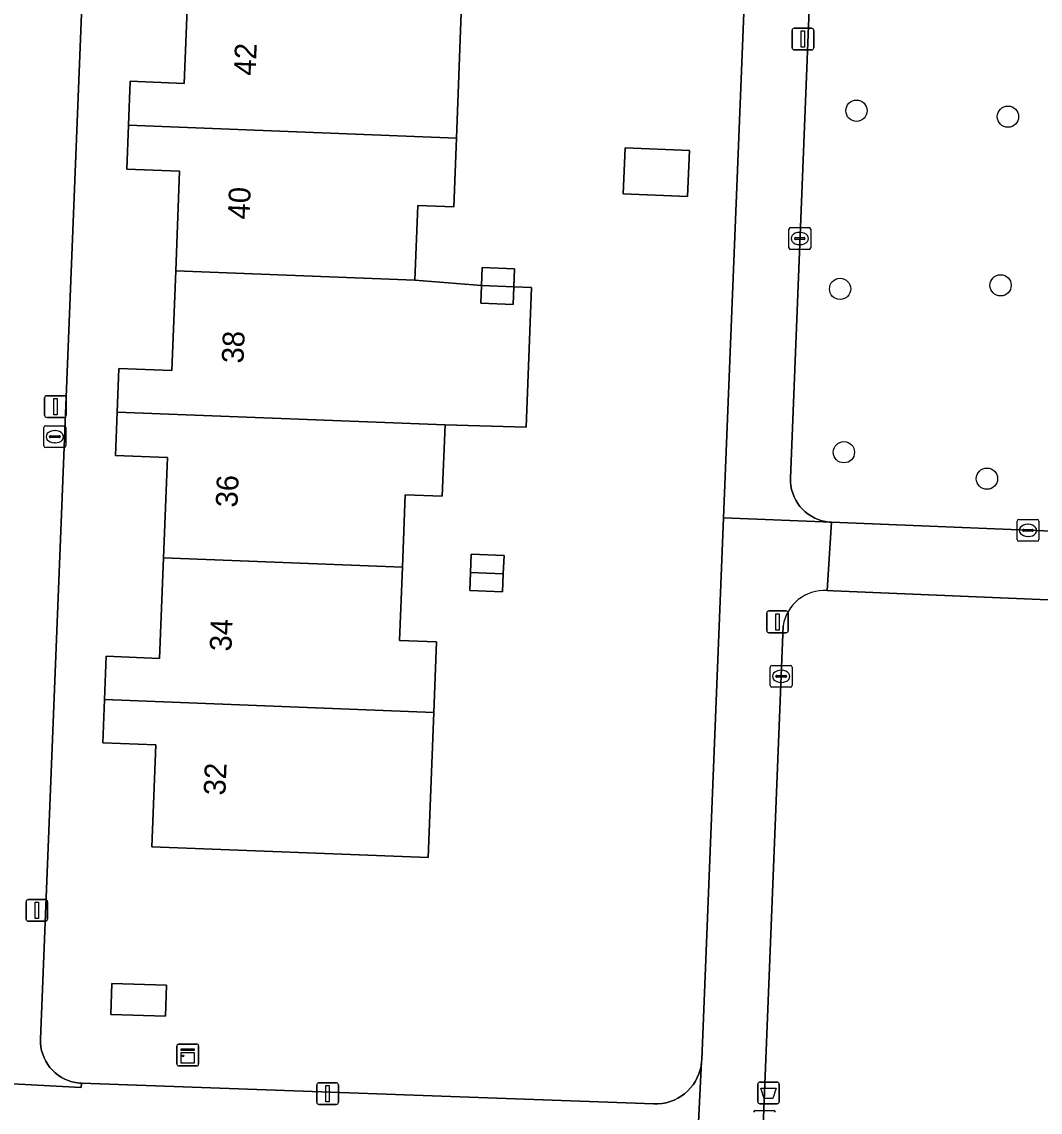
# Model space of a CAD drawing. Extents: x 160786 to 161429, y 386828 to 387485.
# Drawn here: x 161091.8 to 161138.7, y 387047.4 to 387097.5 of the extents above; entities that cross this region are included whole.
import ezdxf

# ---------------------------------------------------------------- set-up
doc = ezdxf.new("R2010")
doc.units = 0
for name, color, linetype in [('IMGEO_Afvalbak', 7, 'Continuous'), ('IMGEO_Boom', 7, 'Continuous'), ('IMGEO_Erf', 7, 'Continuous'), ('IMGEO_Groenvoorziening', 7, 'Continuous'), ('IMGEO_Kast', 7, 'Continuous'), ('IMGEO_Kolk', 7, 'Continuous'), ('IMGEO_Lichtmast', 7, 'Continuous'), ('IMGEO_Pand', 7, 'Continuous'), ('IMGEO_Pand_nummerreeks', 7, 'Continuous'), ('IMGEO_Rioolput', 7, 'Continuous'), ('IMGEO_Voetpad_open', 7, 'Continuous')]:
    doc.layers.add(name, color=color, linetype=linetype)

msp = doc.modelspace()

# ---------------------------------------------------------------- linework, layer by layer
at = {"layer": 'IMGEO_Afvalbak'}
for p, q in [((161125.771, 387048.763), (161126.561, 387048.763)), ((161126.561, 387048.763), (161125.771, 387048.763)), ((161125.671, 387047.863), (161125.671, 387048.663)), ((161125.671, 387048.663), (161125.671, 387047.863)), ((161126.661, 387048.663), (161126.661, 387047.863)), ((161126.661, 387047.863), (161126.661, 387048.663)), ((161126.561, 387047.763), (161125.771, 387047.763)), ((161125.771, 387047.763), (161126.561, 387047.763))]:
    msp.add_line(p, q, dxfattribs=at)
msp.add_lwpolyline([(161125.814, 387048.477), (161126.518, 387048.477), (161126.369, 387048.007), (161125.963, 387048.007), (161125.814, 387048.477)], dxfattribs=at)
for centre, start, end in [((161125.771, 387048.663), 90, 180), ((161125.771, 387048.663), 90, 180), ((161126.561, 387048.663), 0, 90), ((161126.561, 387048.663), 360, 90), ((161125.771, 387047.863), 180, 270), ((161125.771, 387047.863), 180, 270), ((161126.561, 387047.863), 270, 0), ((161126.561, 387047.863), 270, 0)]:
    msp.add_arc(centre, 0.1, start, end, dxfattribs=at)
at = {"layer": 'IMGEO_Boom'}
for centre in [(161130.212, 387093.447), (161137.176, 387093.174), (161136.837, 387085.415), (161129.459, 387085.253), (161129.634, 387077.738), (161136.21, 387076.52)]:
    msp.add_circle(centre, 0.489, dxfattribs=at)
at = {"layer": 'IMGEO_Erf'}
for points in [[(161094.68, 387100.61), (161092.693, 387050.734), (161092.694, 387050.559), (161092.712, 387050.385), (161092.744, 387050.214), (161092.792, 387050.046), (161092.854, 387049.882), (161092.931, 387049.725), (161093.022, 387049.576), (161093.125, 387049.435), (161093.241, 387049.304), (161093.368, 387049.184), (161093.505, 387049.076), (161093.652, 387048.98), (161093.806, 387048.898), (161093.967, 387048.83), (161094.133, 387048.777), (161094.304, 387048.739), (161094.477, 387048.716), (161094.57, 387048.71), (161120.895, 387047.758), (161121.085, 387047.76), (161121.275, 387047.778), (161121.462, 387047.814), (161121.645, 387047.866), (161121.823, 387047.934), (161121.993, 387048.018), (161122.156, 387048.117), (161122.309, 387048.23), (161122.452, 387048.356), (161122.583, 387048.494), (161122.7, 387048.644), (161122.804, 387048.803), (161122.894, 387048.971), (161122.968, 387049.147), (161123.026, 387049.328), (161123.067, 387049.514), (161123.092, 387049.703), (161123.098, 387049.797), (161124.099, 387074.719), (161127.175, 387151.273)], [(161112.071, 387098.797), (161111.813, 387092.188), (161111.69, 387089.03), (161110.043, 387089.094), (161109.909, 387085.648), (161112.969, 387085.409), (161113.001, 387086.236), (161114.484, 387086.178), (161114.452, 387085.351), (161115.266, 387085.317), (161115.024, 387078.887), (161111.297, 387078.995), (161111.168, 387075.71), (161109.465, 387075.777), (161109.335, 387072.443), (161109.203, 387069.076), (161110.907, 387069.009), (161110.78, 387065.768), (161110.519, 387059.095), (161097.808, 387059.592), (161097.991, 387064.277), (161095.561, 387064.372), (161095.639, 387066.36), (161095.717, 387068.351), (161098.164, 387068.255), (161098.345, 387072.872), (161098.525, 387077.488), (161096.14, 387077.581), (161096.218, 387079.585), (161096.297, 387081.591), (161098.732, 387081.496), (161098.911, 387086.078), (161099.09, 387090.661), (161096.655, 387090.756), (161096.734, 387092.778), (161096.813, 387094.802), (161099.297, 387094.705), (161099.476, 387099.29)]]:
    msp.add_lwpolyline(points, dxfattribs=at)
for points in [[(161119.489, 387089.621), (161119.572, 387091.737), (161122.531, 387091.622), (161122.448, 387089.506)], [(161112.466, 387072.204), (161112.499, 387073.041), (161114.005, 387072.983), (161113.973, 387072.146), (161113.94, 387071.323), (161112.434, 387071.382)], [(161098.434, 387051.791), (161095.926, 387051.873), (161095.973, 387053.305), (161098.481, 387053.222)]]:
    msp.add_lwpolyline(points, close=True, dxfattribs=at)
at = {"layer": 'IMGEO_Groenvoorziening'}
for points in [[(161131.407, 387182.665), (161131.384, 387182.078), (161127.179, 387076.544), (161127.18, 387076.369), (161127.198, 387076.195), (161127.23, 387076.024), (161127.278, 387075.856), (161127.34, 387075.692), (161127.417, 387075.535), (161127.508, 387075.386), (161127.611, 387075.245), (161127.727, 387075.114), (161127.854, 387074.994), (161127.991, 387074.886), (161128.138, 387074.79), (161128.292, 387074.708), (161128.453, 387074.64), (161128.619, 387074.587), (161128.79, 387074.549), (161128.963, 387074.526), (161129.056, 387074.52), (161141.468, 387074.009), (161145.662, 387177.089)], [(161150.759, 387070.455), (161129.133, 387071.365), (161128.864, 387071.378)], [(161126.838, 387069.748), (161124.044, 387000), (161122.553, 386963.852)]]:
    msp.add_lwpolyline(points, dxfattribs=at)
msp.add_arc((161128.747, 387069.45), 1.932, 86.5201, 171.1161, dxfattribs=at)
at = {"layer": 'IMGEO_Kast'}
for p, q in [((161098.961, 387049.58), (161098.961, 387050.421)), ((161098.961, 387050.421), (161098.961, 387049.58)), ((161099.036, 387050.505), (161099.877, 387050.505)), ((161099.877, 387050.505), (161099.036, 387050.505)), ((161099.961, 387050.43), (161099.961, 387049.589)), ((161099.961, 387049.589), (161099.961, 387050.43)), ((161099.886, 387049.505), (161099.045, 387049.505)), ((161099.045, 387049.505), (161099.886, 387049.505))]:
    msp.add_line(p, q, dxfattribs=at)
for points in [[(161099.156, 387050.295), (161099.756, 387050.295), (161099.756, 387050.21), (161099.156, 387050.21), (161099.156, 387050.295)], [(161099.156, 387050.12), (161099.756, 387050.12), (161099.756, 387049.631), (161099.156, 387049.631), (161099.156, 387050.12)]]:
    msp.add_lwpolyline(points, dxfattribs=at)
msp.add_circle((161099.24, 387049.969), 0.0377, dxfattribs=at)
for centre, start, end in [((161099.039, 387050.427), 92.4484, 184.2845), ((161099.039, 387050.427), 92.4484, 184.2845), ((161099.883, 387050.427), 2.4484, 94.2845), ((161099.883, 387050.427), 2.4484, 94.2845), ((161099.039, 387049.583), 182.4484, 274.2845), ((161099.039, 387049.583), 182.4484, 274.2845), ((161099.883, 387049.583), 272.4484, 4.2845), ((161099.883, 387049.583), 272.4484, 4.2845)]:
    msp.add_arc(centre, 0.0779, start, end, dxfattribs=at)
at = {"layer": 'IMGEO_Kolk'}
for p, q in [((161127.105, 387087.142), (161127.105, 387087.994)), ((161127.18, 387088.068), (161128.032, 387088.068)), ((161127.593, 387087.848), (161127.618, 387087.848)), ((161128.106, 387087.994), (161128.106, 387087.142)), ((161127.364, 387087.562), (161127.364, 387087.574)), ((161127.802, 387087.525), (161127.404, 387087.525)), ((161127.407, 387087.611), (161127.805, 387087.611)), ((161127.848, 387087.574), (161127.848, 387087.562)), ((161128.032, 387087.068), (161127.18, 387087.068)), ((161127.616, 387087.288), (161127.591, 387087.288)), ((161137.599, 387073.716), (161137.599, 387074.568)), ((161137.674, 387074.642), (161138.526, 387074.642)), ((161138.087, 387074.422), (161138.112, 387074.422)), ((161138.6, 387074.568), (161138.6, 387073.716)), ((161137.858, 387074.136), (161137.858, 387074.148)), ((161138.296, 387074.099), (161137.898, 387074.099)), ((161137.901, 387074.185), (161138.299, 387074.185)), ((161138.11, 387073.862), (161138.085, 387073.862)), ((161138.342, 387074.148), (161138.342, 387074.136)), ((161138.526, 387073.642), (161137.674, 387073.642)), ((161126.25, 387067.001), (161126.25, 387067.853)), ((161126.325, 387067.927), (161127.177, 387067.927)), ((161127.251, 387067.853), (161127.251, 387067.001)), ((161126.509, 387067.421), (161126.509, 387067.433)), ((161126.947, 387067.384), (161126.549, 387067.384)), ((161126.552, 387067.47), (161126.95, 387067.47)), ((161126.738, 387067.707), (161126.763, 387067.707)), ((161126.993, 387067.433), (161126.993, 387067.421)), ((161127.177, 387066.927), (161126.325, 387066.927)), ((161126.761, 387067.147), (161126.736, 387067.147)), ((161125.556, 387047.452), (161126.408, 387047.452))]:
    msp.add_line(p, q, dxfattribs=at)
for points in [[(161127.105, 387087.142), (161127.105, 387087.994)], [(161127.18, 387088.068), (161128.032, 387088.068)], [(161128.106, 387087.994), (161128.106, 387087.142)], [(161128.032, 387087.068), (161127.18, 387087.068)], [(161137.599, 387073.716), (161137.599, 387074.568)], [(161137.674, 387074.642), (161138.526, 387074.642)], [(161138.6, 387074.568), (161138.6, 387073.716)], [(161138.526, 387073.642), (161137.674, 387073.642)], [(161126.25, 387067.001), (161126.25, 387067.853)], [(161126.325, 387067.927), (161127.177, 387067.927)], [(161127.251, 387067.853), (161127.251, 387067.001)], [(161127.177, 387066.927), (161126.325, 387066.927)], [(161125.556, 387047.452), (161126.408, 387047.452)]]:
    msp.add_lwpolyline(points, dxfattribs=at)
for centre, radius, start, end in [((161127.182, 387087.992), 0.0765, 91.552, 178.448), ((161127.182, 387087.992), 0.0765, 91.552, 178.448), ((161128.03, 387087.992), 0.0765, 1.552, 88.448), ((161128.03, 387087.992), 0.0765, 1.552, 88.448), ((161127.404, 387087.571), 0.0403, 85.8775, 175.7526), ((161127.401, 387087.561), 0.0366, 178.938, 274.7102), ((161127.805, 387087.568), 0.043, 264.8664, 352.4533), ((161127.809, 387087.573), 0.0386, 1.7309, 96.639), ((161127.182, 387087.144), 0.0765, 181.552, 268.448), ((161127.182, 387087.144), 0.0765, 181.552, 268.448), ((161128.03, 387087.144), 0.0765, 271.552, 358.448), ((161128.03, 387087.144), 0.0765, 271.552, 358.448), ((161137.676, 387074.566), 0.0765, 91.552, 178.448), ((161137.676, 387074.566), 0.0765, 91.552, 178.448), ((161138.524, 387074.566), 0.0765, 1.552, 88.448), ((161138.524, 387074.566), 0.0765, 1.552, 88.448), ((161137.898, 387074.145), 0.0403, 85.8775, 175.7526), ((161137.895, 387074.135), 0.0366, 178.938, 274.7102), ((161138.299, 387074.142), 0.043, 264.8664, 352.4533), ((161138.303, 387074.147), 0.0386, 1.7309, 96.639), ((161137.676, 387073.718), 0.0765, 181.552, 268.448), ((161137.676, 387073.718), 0.0765, 181.552, 268.448), ((161138.524, 387073.718), 0.0765, 271.552, 358.448), ((161138.524, 387073.718), 0.0765, 271.552, 358.448), ((161126.327, 387067.851), 0.0765, 91.552, 178.448), ((161126.327, 387067.851), 0.0765, 91.552, 178.448), ((161127.175, 387067.851), 0.0765, 1.552, 88.448), ((161127.175, 387067.851), 0.0765, 1.552, 88.448), ((161126.549, 387067.43), 0.0403, 85.8775, 175.7526), ((161126.546, 387067.42), 0.0366, 178.938, 274.7102), ((161126.95, 387067.427), 0.043, 264.8664, 352.4533), ((161126.954, 387067.432), 0.0386, 1.7309, 96.639), ((161126.327, 387067.003), 0.0765, 181.552, 268.448), ((161126.327, 387067.003), 0.0765, 181.552, 268.448), ((161127.175, 387067.003), 0.0765, 271.552, 358.448), ((161127.175, 387067.003), 0.0765, 271.552, 358.448), ((161125.558, 387047.376), 0.0765, 91.552, 178.448), ((161125.558, 387047.376), 0.0765, 91.552, 178.448), ((161126.406, 387047.376), 0.0765, 1.552, 88.448), ((161126.406, 387047.376), 0.0765, 1.552, 88.448)]:
    msp.add_arc(centre, radius, start, end, dxfattribs=at)
for centre, major_axis, ratio, start_param, end_param in [((161127.592, 387087.568), (-0.387, 0.002), 0.722429, 4.712389, 7.853982), ((161127.617, 387087.568), (-0.39, 0.002), 0.717154, 1.570796, 4.712389), ((161138.086, 387074.142), (-0.387, 0.002), 0.722429, 4.712389, 7.853982), ((161138.111, 387074.142), (-0.39, 0.002), 0.717154, 1.570796, 4.712389), ((161126.737, 387067.427), (-0.387, 0.002), 0.722429, 4.712389, 7.853982), ((161126.762, 387067.427), (-0.39, 0.002), 0.717154, 1.570796, 4.712389)]:
    msp.add_ellipse(centre, major_axis=major_axis, ratio=ratio, start_param=start_param, end_param=end_param, dxfattribs=at)
at = {"layer": 'IMGEO_Lichtmast'}
for p, q in [((161127.254, 387096.342), (161127.254, 387097.142)), ((161127.254, 387097.142), (161127.254, 387096.342)), ((161127.354, 387097.242), (161128.144, 387097.242)), ((161128.144, 387097.242), (161127.354, 387097.242)), ((161128.244, 387097.142), (161128.244, 387096.342)), ((161128.244, 387096.342), (161128.244, 387097.142)), ((161128.144, 387096.242), (161127.354, 387096.242)), ((161127.354, 387096.242), (161128.144, 387096.242)), ((161092.981, 387080.339), (161093.771, 387080.339)), ((161093.771, 387080.339), (161092.981, 387080.339)), ((161092.881, 387079.439), (161092.881, 387080.239)), ((161092.881, 387080.239), (161092.881, 387079.439)), ((161093.871, 387080.239), (161093.871, 387079.439)), ((161093.871, 387079.439), (161093.871, 387080.239)), ((161093.771, 387079.339), (161092.981, 387079.339)), ((161092.981, 387079.339), (161093.771, 387079.339)), ((161126.085, 387069.534), (161126.085, 387070.334)), ((161126.085, 387070.334), (161126.085, 387069.534)), ((161126.185, 387070.434), (161126.975, 387070.434)), ((161126.975, 387070.434), (161126.185, 387070.434)), ((161127.075, 387070.334), (161127.075, 387069.534)), ((161127.075, 387069.534), (161127.075, 387070.334)), ((161126.975, 387069.434), (161126.185, 387069.434)), ((161126.185, 387069.434), (161126.975, 387069.434)), ((161092.028, 387056.261), (161092.028, 387057.061)), ((161092.028, 387057.061), (161092.028, 387056.261)), ((161092.128, 387057.161), (161092.918, 387057.161)), ((161092.918, 387057.161), (161092.128, 387057.161)), ((161093.018, 387057.061), (161093.018, 387056.261)), ((161093.018, 387056.261), (161093.018, 387057.061)), ((161092.918, 387056.161), (161092.128, 387056.161)), ((161092.128, 387056.161), (161092.918, 387056.161)), ((161105.497, 387048.732), (161106.287, 387048.732)), ((161106.287, 387048.732), (161105.497, 387048.732)), ((161105.397, 387047.832), (161105.397, 387048.632)), ((161105.397, 387048.632), (161105.397, 387047.832)), ((161106.387, 387048.632), (161106.387, 387047.832)), ((161106.387, 387047.832), (161106.387, 387048.632)), ((161106.287, 387047.732), (161105.497, 387047.732)), ((161105.497, 387047.732), (161106.287, 387047.732))]:
    msp.add_line(p, q, dxfattribs=at)
for points in [[(161127.674, 387097.117), (161127.824, 387097.117), (161127.824, 387096.367), (161127.674, 387096.367), (161127.674, 387097.117)], [(161093.301, 387080.214), (161093.451, 387080.214), (161093.451, 387079.464), (161093.301, 387079.464), (161093.301, 387080.214)], [(161126.505, 387070.309), (161126.655, 387070.309), (161126.655, 387069.559), (161126.505, 387069.559), (161126.505, 387070.309)], [(161092.448, 387057.036), (161092.598, 387057.036), (161092.598, 387056.286), (161092.448, 387056.286), (161092.448, 387057.036)], [(161105.817, 387048.607), (161105.967, 387048.607), (161105.967, 387047.857), (161105.817, 387047.857), (161105.817, 387048.607)]]:
    msp.add_lwpolyline(points, dxfattribs=at)
for centre, start, end in [((161127.354, 387097.142), 90, 180), ((161127.354, 387097.142), 90, 180), ((161128.144, 387097.142), 0, 90), ((161128.144, 387097.142), 360, 90), ((161127.354, 387096.342), 180, 270), ((161127.354, 387096.342), 180, 270), ((161128.144, 387096.342), 270, 0), ((161128.144, 387096.342), 270, 0), ((161092.981, 387080.239), 90, 180), ((161092.981, 387080.239), 90, 180), ((161093.771, 387080.239), 0, 90), ((161093.771, 387080.239), 360, 90), ((161092.981, 387079.439), 180, 270), ((161092.981, 387079.439), 180, 270), ((161093.771, 387079.439), 270, 0), ((161093.771, 387079.439), 270, 0), ((161126.185, 387070.334), 90, 180), ((161126.185, 387070.334), 90, 180), ((161126.975, 387070.334), 0, 90), ((161126.975, 387070.334), 360, 90), ((161126.185, 387069.534), 180, 270), ((161126.185, 387069.534), 180, 270), ((161126.975, 387069.534), 270, 0), ((161126.975, 387069.534), 270, 0), ((161092.128, 387057.061), 90, 180), ((161092.128, 387057.061), 90, 180), ((161092.918, 387057.061), 0, 90), ((161092.918, 387057.061), 360, 90), ((161092.128, 387056.261), 180, 270), ((161092.128, 387056.261), 180, 270), ((161092.918, 387056.261), 270, 0), ((161092.918, 387056.261), 270, 0), ((161105.497, 387048.632), 90, 180), ((161105.497, 387048.632), 90, 180), ((161106.287, 387048.632), 0, 90), ((161106.287, 387048.632), 360, 90), ((161105.497, 387047.832), 180, 270), ((161105.497, 387047.832), 180, 270), ((161106.287, 387047.832), 270, 0), ((161106.287, 387047.832), 270, 0)]:
    msp.add_arc(centre, 0.1, start, end, dxfattribs=at)
at = {"layer": 'IMGEO_Pand'}
for points in [[(161111.813, 387092.188), (161112.071, 387098.797), (161099.476, 387099.29), (161099.297, 387094.705), (161096.813, 387094.802), (161096.734, 387092.778)], [(161111.813, 387092.188), (161096.734, 387092.778), (161096.655, 387090.756), (161099.09, 387090.661), (161098.911, 387086.078), (161109.909, 387085.648), (161110.043, 387089.094), (161111.69, 387089.03)], [(161119.489, 387089.621), (161122.448, 387089.506), (161122.531, 387091.622), (161119.572, 387091.737)], [(161114.452, 387085.351), (161114.42, 387084.53), (161112.937, 387084.587), (161112.969, 387085.409), (161109.909, 387085.648), (161098.911, 387086.078), (161098.732, 387081.496), (161096.297, 387081.591), (161096.218, 387079.585), (161111.297, 387078.995), (161115.024, 387078.887), (161115.266, 387085.317)], [(161112.969, 387085.409), (161114.452, 387085.351), (161114.484, 387086.178), (161113.001, 387086.236)], [(161114.452, 387085.351), (161112.969, 387085.409), (161112.937, 387084.587), (161114.42, 387084.53)], [(161111.297, 387078.995), (161096.218, 387079.585), (161096.14, 387077.581), (161098.525, 387077.488), (161098.345, 387072.872), (161109.335, 387072.443), (161109.465, 387075.777), (161111.168, 387075.71)], [(161109.335, 387072.443), (161098.345, 387072.872), (161098.164, 387068.255), (161095.717, 387068.351), (161095.639, 387066.36), (161110.78, 387065.768), (161110.907, 387069.009), (161109.203, 387069.076)], [(161112.466, 387072.204), (161113.973, 387072.146), (161114.005, 387072.983), (161112.499, 387073.041)], [(161113.973, 387072.146), (161112.466, 387072.204), (161112.434, 387071.382), (161113.94, 387071.323)], [(161095.639, 387066.36), (161095.561, 387064.372), (161097.991, 387064.277), (161097.808, 387059.592), (161110.519, 387059.095), (161110.78, 387065.768)], [(161095.926, 387051.873), (161098.434, 387051.791), (161098.481, 387053.222), (161095.973, 387053.305)]]:
    msp.add_lwpolyline(points, close=True, dxfattribs=at)
at = {"layer": 'IMGEO_Rioolput'}
for p, q in [((161092.849, 387078.025), (161092.849, 387078.877)), ((161092.924, 387078.951), (161093.776, 387078.951)), ((161093.85, 387078.877), (161093.85, 387078.025)), ((161093.108, 387078.445), (161093.108, 387078.457)), ((161093.546, 387078.408), (161093.148, 387078.408)), ((161093.151, 387078.494), (161093.549, 387078.494)), ((161093.337, 387078.731), (161093.362, 387078.731)), ((161093.592, 387078.457), (161093.592, 387078.445)), ((161093.776, 387077.951), (161092.924, 387077.951)), ((161093.36, 387078.171), (161093.335, 387078.171))]:
    msp.add_line(p, q, dxfattribs=at)
for points in [[(161092.849, 387078.025), (161092.849, 387078.877)], [(161092.924, 387078.951), (161093.776, 387078.951)], [(161093.85, 387078.877), (161093.85, 387078.025)], [(161093.776, 387077.951), (161092.924, 387077.951)]]:
    msp.add_lwpolyline(points, dxfattribs=at)
for centre, radius, start, end in [((161092.926, 387078.875), 0.0765, 91.552, 178.448), ((161092.926, 387078.875), 0.0765, 91.552, 178.448), ((161093.774, 387078.875), 0.0765, 1.552, 88.448), ((161093.774, 387078.875), 0.0765, 1.552, 88.448), ((161093.148, 387078.454), 0.0403, 85.8775, 175.7526), ((161093.145, 387078.444), 0.0366, 178.938, 274.7102), ((161093.549, 387078.451), 0.043, 264.8664, 352.4533), ((161093.553, 387078.456), 0.0386, 1.7309, 96.639), ((161092.926, 387078.027), 0.0765, 181.552, 268.448), ((161092.926, 387078.027), 0.0765, 181.552, 268.448), ((161093.774, 387078.027), 0.0765, 271.552, 358.448), ((161093.774, 387078.027), 0.0765, 271.552, 358.448)]:
    msp.add_arc(centre, radius, start, end, dxfattribs=at)
for centre, major_axis, ratio, start_param, end_param in [((161093.336, 387078.451), (-0.387, 0.002), 0.722429, 4.712389, 7.853982), ((161093.361, 387078.451), (-0.39, 0.002), 0.717154, 1.570796, 4.712389)]:
    msp.add_ellipse(centre, major_axis=major_axis, ratio=ratio, start_param=start_param, end_param=end_param, dxfattribs=at)
at = {"layer": 'IMGEO_Voetpad_open'}
for points in [[(161127.175, 387151.273), (161124.099, 387074.719), (161129.056, 387074.52), (161128.963, 387074.526), (161128.79, 387074.549), (161128.619, 387074.587), (161128.453, 387074.64), (161128.292, 387074.708), (161128.138, 387074.79), (161127.991, 387074.886), (161127.854, 387074.994), (161127.727, 387075.114), (161127.611, 387075.245), (161127.508, 387075.386), (161127.417, 387075.535), (161127.34, 387075.692), (161127.278, 387075.856), (161127.23, 387076.024), (161127.198, 387076.195), (161127.18, 387076.369), (161127.179, 387076.544), (161131.384, 387182.078)], [(161089.667, 387048.768), (161094.559, 387048.51), (161094.57, 387048.71), (161094.477, 387048.716), (161094.304, 387048.739), (161094.133, 387048.777), (161093.967, 387048.83), (161093.806, 387048.898), (161093.652, 387048.98), (161093.505, 387049.076), (161093.368, 387049.184), (161093.241, 387049.304), (161093.125, 387049.435), (161093.022, 387049.576), (161092.931, 387049.725), (161092.854, 387049.882), (161092.792, 387050.046), (161092.744, 387050.214), (161092.712, 387050.385), (161092.694, 387050.559), (161092.693, 387050.734), (161094.68, 387100.61)], [(161128.864, 387071.378), (161129.056, 387074.52), (161124.099, 387074.719), (161123.098, 387049.797), (161123.092, 387049.703), (161122.751, 387042.869), (161122.753, 387042.692), (161122.596, 387038.706), (161121.076, 387000), (161119.475, 386959.244), (161118.604, 386937.102)], [(161155.473, 387073.431), (161147.279, 387073.767), (161141.468, 387074.009), (161129.056, 387074.52), (161128.864, 387071.378), (161129.133, 387071.365), (161150.759, 387070.455), (161150.793, 387070.458), (161157.068, 387070.064), (161184.654, 387069.093), (161190.576, 387068.744), (161208.66, 387068.005), (161208.877, 387067.997), (161209.096, 387067.988), (161209.41, 387067.975), (161209.768, 387067.943)], [(161120.37, 386911.783), (161120.564, 386917.225), (161120.797, 386923.755), (161120.97, 386928.628), (161121.017, 386929.934), (161121.473, 386936.897), (161122.253, 386956.657), (161122.251, 386956.693), (161122.549, 386963.816), (161122.553, 386963.852), (161124.044, 387000), (161126.838, 387069.748)], [(161123.092, 387049.703), (161123.067, 387049.514), (161123.026, 387049.328), (161122.968, 387049.147), (161122.894, 387048.971), (161122.804, 387048.803), (161122.7, 387048.644), (161122.583, 387048.494), (161122.452, 387048.356), (161122.309, 387048.23), (161122.156, 387048.117), (161121.993, 387048.018), (161121.823, 387047.934), (161121.645, 387047.866), (161121.462, 387047.814), (161121.275, 387047.778), (161121.085, 387047.76), (161120.895, 387047.758), (161094.57, 387048.71), (161094.559, 387048.51), (161089.667, 387048.768), (161089.678, 387048.968), (161043.302, 387050.776), (161036.645, 387051.029)], [(161122.751, 387042.869), (161123.092, 387049.703)]]:
    msp.add_lwpolyline(points, dxfattribs=at)
msp.add_arc((161128.747, 387069.45), 1.932, 86.5201, 171.1161, dxfattribs=at)

# ---------------------------------------------------------------- texts
at = {"layer": 'IMGEO_Pand_nummerreeks'}
for s, rotation, p in [('42', 87.6017, (161102.576, 387095.049)), ('40', 87.5995, (161102.299, 387088.432)), ('38', 87.5995, (161102.021, 387081.81)), ('36', 87.5995, (161101.744, 387075.184)), ('34', 87.5995, (161101.466, 387068.562)), ('32', 87.6017, (161101.189, 387061.938))]:
    msp.add_text(s, height=1, rotation=rotation, dxfattribs=at).set_placement(p)

doc.saveas('drawing.dxf')
